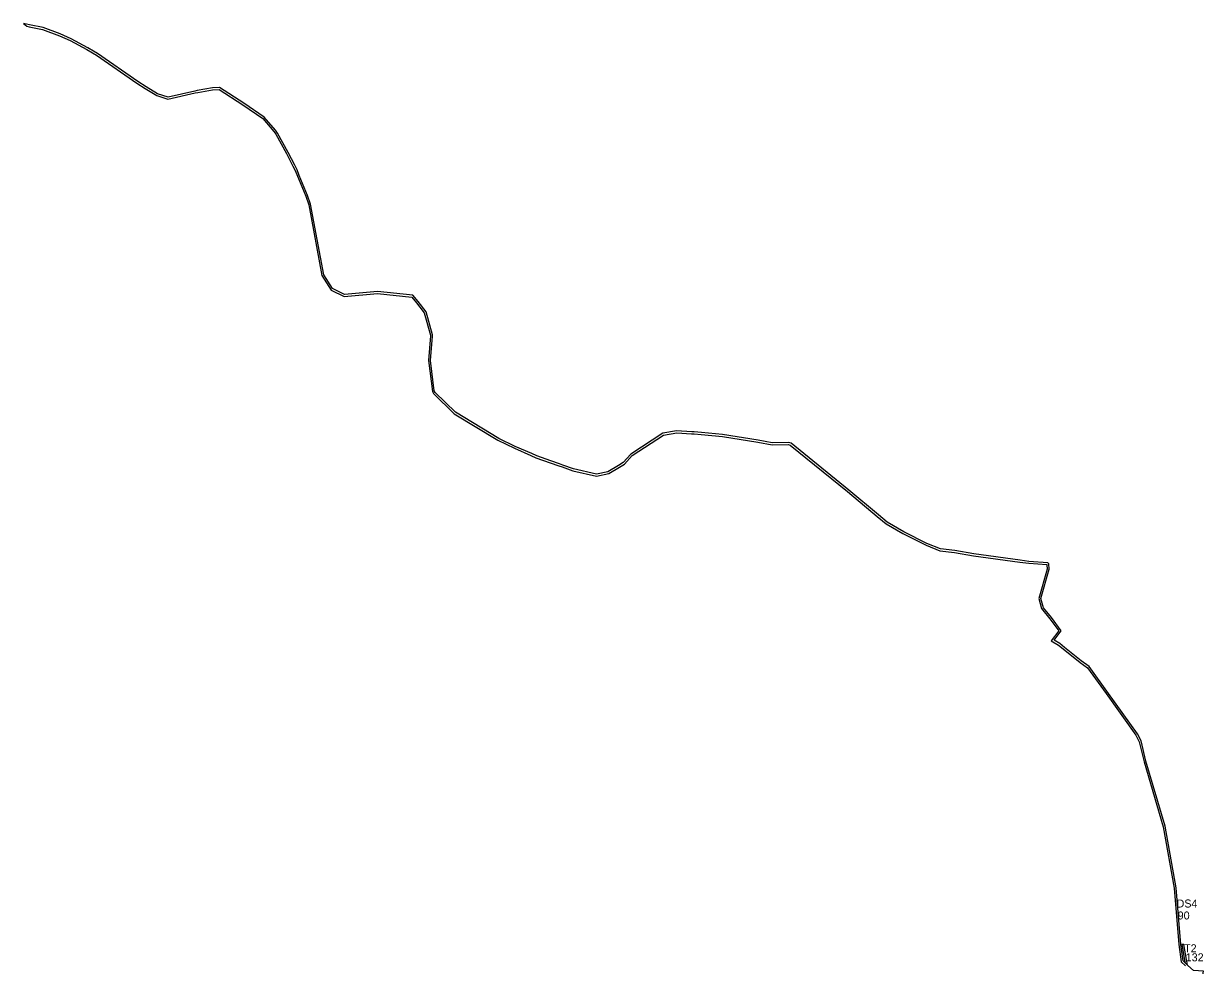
# Model space of a CAD drawing. Extents: x -477001 to -465642, y -1158278 to -1150672.
# Drawn here: x -477001 to -475233, y -1152085 to -1150672 of the extents above; entities that cross this region are included whole.
import ezdxf

# ---------------------------------------------------------------- set-up
doc = ezdxf.new("R2010")
doc.units = 0
for name, color, linetype in [('VPS_id', 7, 'Continuous'), ('VPS_n', 7, 'Continuous'), ('vyvlastneni_n', 7, 'Continuous')]:
    doc.layers.add(name, color=color, linetype=linetype)

msp = doc.modelspace()

# ---------------------------------------------------------------- linework, layer by layer
at = {"layer": 'VPS_n'}
for p, q in [((-477001.2, -1150672.5), (-476996.6, -1150676.4)), ((-475449.4, -1151582.8), (-475460.9, -1151597.8)), ((-475456.5, -1151596.9), (-475445.7, -1151582.8)), ((-475406.2, -1151638.6), (-475378.6, -1151677.1)), ((-475375, -1151677.1), (-475404, -1151636.5)), ((-475328.8, -1151749.3), (-475321.6, -1151779.5)), ((-475318.7, -1151778.7), (-475326, -1151748.2)), ((-475261.9, -1152053.4), (-475265, -1152053.3)), ((-475265, -1152053.3), (-475261, -1152076.8)), ((-475258.1, -1152076), (-475261.9, -1152053.4)), ((-475265.9, -1152079.5), (-475259.5, -1152085.3)), ((-475260, -1152080.8), (-475263, -1152078)), ((-475261, -1152076.8), (-475260.3, -1152079.1)), ((-475260.3, -1152079.1), (-475260, -1152080.8)), ((-475256.7, -1152083.9), (-475260, -1152080.8)), ((-475260, -1152080.8), (-475256.7, -1152083.9)), ((-475258.1, -1152076.1), (-475258.1, -1152076)), ((-475257.4, -1152078.2), (-475258.1, -1152076.1)), ((-475256.7, -1152083.9), (-475256.5, -1152084.1)), ((-475256.5, -1152084.1), (-475256.5, -1152084.1))]:
    msp.add_line(p, q, dxfattribs=at)
for points in [[(-476718.2, -1150768.8), (-476740.8, -1150772.9), (-476744.5, -1150773.6), (-476784.7, -1150782.8), (-476800.5, -1150777.7), (-476817.6, -1150767.5), (-476830, -1150759.4), (-476890.5, -1150717.2), (-476896.5, -1150713.7), (-476904.7, -1150708.7), (-476929.9, -1150695.2), (-476946.4, -1150688), (-476972.1, -1150678.5), (-476992.2, -1150674.1), (-477001.2, -1150672.5)], [(-476996.6, -1150676.4), (-476992.8, -1150677.1), (-476973, -1150681.4), (-476947.5, -1150690.8), (-476931.2, -1150697.9), (-476906.2, -1150711.3), (-476898.1, -1150716.3), (-476892.1, -1150719.8), (-476831.7, -1150761.9), (-476819.2, -1150770), (-476801.7, -1150780.5), (-476784.9, -1150785.9), (-476743.9, -1150776.5), (-476740.2, -1150775.8), (-476717.9, -1150771.8)], [(-475445.7, -1151582.8), (-475460.3, -1151563.2), (-475472.4, -1151548.3), (-475476.3, -1151534.3), (-475463.9, -1151490.8), (-475464.3, -1151482.7), (-475466, -1151480.9), (-475494.2, -1151478.9), (-475507.2, -1151477.2), (-475576.5, -1151467.6), (-475605.2, -1151462.8), (-475626.9, -1151460.1), (-475647, -1151452.1), (-475681.7, -1151434.5), (-475706.7, -1151420), (-475719.8, -1151409.3), (-475764.2, -1151371.9), (-475850.4, -1151301.7), (-475854, -1151300.5), (-475878.9, -1151301.2), (-475900.1, -1151297.2), (-475953.3, -1151288.5), (-475985.1, -1151285.7), (-475995.8, -1151284.8), (-475999.7, -1151284.6), (-476022.3, -1151283.2), (-476042.9, -1151286.7), (-476091.1, -1151317.9), (-476102.2, -1151330.7), (-476109.6, -1151335), (-476125.2, -1151344.5), (-476142.4, -1151347.9), (-476176.8, -1151340.1), (-476193, -1151334.4), (-476197.9, -1151332.7), (-476210.9, -1151328.2), (-476231.9, -1151320.7), (-476239.5, -1151317.2), (-476264.1, -1151306.5), (-476289, -1151294.4), (-476353.8, -1151255), (-476384.3, -1151225.5), (-476385.5, -1151223.1), (-476391.4, -1151177.6), (-476388.2, -1151141.2), (-476388, -1151139.4), (-476397.8, -1151104.9), (-476409.8, -1151089.1), (-476417.6, -1151079.8), (-476470.7, -1151074.2), (-476520.3, -1151078.5), (-476538.3, -1151069.8), (-476551.3, -1151049.3), (-476570.9, -1150943.2), (-476575.5, -1150930.1), (-476588, -1150900.4), (-476591.3, -1150891.6), (-476594.8, -1150884.9), (-476604.5, -1150866), (-476620.6, -1150837), (-476623.5, -1150832.4), (-476640.6, -1150812.6), (-476670.9, -1150791.7), (-476707.5, -1150768.5), (-476718.2, -1150768.8)], [(-476717.9, -1150771.8), (-476708.3, -1150771.5), (-476672.5, -1150794.2), (-476642.7, -1150814.8), (-476625.9, -1150834.2), (-476623.2, -1150838.5), (-476607.2, -1150867.4), (-476597.4, -1150886.3), (-476594, -1150892.9), (-476590.8, -1150901.5), (-476578.3, -1150931.2), (-476573.8, -1150944), (-476554.2, -1151050.4), (-476540.4, -1151072.1), (-476520.8, -1151081.5), (-476470.8, -1151077.2), (-476419.1, -1151082.6), (-476412.2, -1151091), (-476400.6, -1151106.3), (-476391.1, -1151139.7), (-476391.2, -1151140.9), (-476394.4, -1151177.7), (-476388.4, -1151223.9), (-476386.8, -1151227.3), (-476355.6, -1151257.4), (-476290.4, -1151297.1), (-476265.4, -1151309.3), (-476240.7, -1151320), (-476233.1, -1151323.5), (-476211.9, -1151331), (-476198.9, -1151335.6), (-476193.9, -1151337.3), (-476177.7, -1151343), (-476142.5, -1151350.9), (-476124.1, -1151347.3), (-476108.1, -1151337.6), (-476100.2, -1151333.1), (-476089.1, -1151320.2), (-476041.8, -1151289.6), (-476022.1, -1151286.3), (-475999.9, -1151287.6), (-475996.1, -1151287.8), (-475985.3, -1151288.7), (-475953.7, -1151291.5), (-475900.6, -1151300.2), (-475879.1, -1151304.2), (-475854.5, -1151303.5), (-475851.9, -1151304.4), (-475766.1, -1151374.2), (-475721.7, -1151411.6), (-475708.4, -1151422.5), (-475683.2, -1151437.2), (-475648.2, -1151454.8), (-475627.6, -1151463.1), (-475605.6, -1151465.8), (-475577, -1151470.6), (-475507.6, -1151480.2), (-475494.5, -1151481.8), (-475467.4, -1151483.8), (-475467.3, -1151484), (-475467, -1151490.5), (-475479.4, -1151534.3), (-475475.2, -1151549.7), (-475462.7, -1151565), (-475449.4, -1151582.8)], [(-475460.9, -1151597.8), (-475449.7, -1151604.6), (-475442.7, -1151610.1), (-475417.4, -1151630.5), (-475406.2, -1151638.6)], [(-475404, -1151636.5), (-475415.6, -1151628.1), (-475440.8, -1151607.8), (-475448, -1151602.1), (-475456.5, -1151596.9)], [(-475378.6, -1151677.1), (-475334.1, -1151739.3), (-475328.8, -1151749.3)], [(-475326, -1151748.2), (-475331.6, -1151737.7), (-475375, -1151677.1)], [(-475321.6, -1151779.5), (-475293, -1151876.7), (-475276.6, -1151969), (-475269.2, -1152053.6), (-475265.9, -1152079.5)], [(-475263, -1152078), (-475266.2, -1152053.3), (-475273.6, -1151968.6), (-475290.1, -1151876.1), (-475318.7, -1151778.7)], [(-475256.5, -1152084.1), (-475257.4, -1152078.4), (-475257.4, -1152078.2)], [(-475245.1, -1152165.1), (-475244.5, -1152159.7), (-475239.6, -1152134.5), (-475232.6, -1152093.5), (-475247.3, -1152092.5), (-475255.7, -1152084.7), (-475256.5, -1152084.1), (-475256.7, -1152083.9)]]:
    msp.add_lwpolyline(points, dxfattribs=at)
at = {"layer": 'vyvlastneni_n'}
for p, q in [((-477001.2, -1150672.5), (-476996.6, -1150676.4)), ((-475449.4, -1151582.8), (-475460.9, -1151597.8)), ((-475456.5, -1151596.9), (-475445.7, -1151582.8)), ((-475406.2, -1151638.6), (-475378.6, -1151677.1)), ((-475375, -1151677.1), (-475404, -1151636.5)), ((-475328.8, -1151749.3), (-475321.6, -1151779.5)), ((-475318.7, -1151778.7), (-475326, -1151748.2)), ((-475261.9, -1152053.4), (-475265, -1152053.3)), ((-475265, -1152053.3), (-475261, -1152076.8)), ((-475258.1, -1152076), (-475261.9, -1152053.4)), ((-475265.9, -1152079.5), (-475259.5, -1152085.3)), ((-475260, -1152080.8), (-475263, -1152078)), ((-475261, -1152076.8), (-475260.3, -1152079.1)), ((-475260.3, -1152079.1), (-475260, -1152080.8)), ((-475256.7, -1152083.9), (-475260, -1152080.8)), ((-475260, -1152080.8), (-475256.7, -1152083.9)), ((-475258.1, -1152076.1), (-475258.1, -1152076)), ((-475257.4, -1152078.2), (-475258.1, -1152076.1)), ((-475256.7, -1152083.9), (-475256.5, -1152084.1)), ((-475256.5, -1152084.1), (-475256.5, -1152084.1))]:
    msp.add_line(p, q, dxfattribs=at)
for points in [[(-476718.2, -1150768.8), (-476740.8, -1150772.9), (-476744.5, -1150773.6), (-476784.7, -1150782.8), (-476800.5, -1150777.7), (-476817.6, -1150767.5), (-476830, -1150759.4), (-476890.5, -1150717.2), (-476896.5, -1150713.7), (-476904.7, -1150708.7), (-476929.9, -1150695.2), (-476946.4, -1150688), (-476972.1, -1150678.5), (-476992.2, -1150674.1), (-477001.2, -1150672.5)], [(-476996.6, -1150676.4), (-476992.8, -1150677.1), (-476973, -1150681.4), (-476947.5, -1150690.8), (-476931.2, -1150697.9), (-476906.2, -1150711.3), (-476898.1, -1150716.3), (-476892.1, -1150719.8), (-476831.7, -1150761.9), (-476819.2, -1150770), (-476801.7, -1150780.5), (-476784.9, -1150785.9), (-476743.9, -1150776.5), (-476740.2, -1150775.8), (-476717.9, -1150771.8)], [(-475445.7, -1151582.8), (-475460.3, -1151563.2), (-475472.4, -1151548.3), (-475476.3, -1151534.3), (-475463.9, -1151490.8), (-475464.3, -1151482.7), (-475466, -1151480.9), (-475494.2, -1151478.9), (-475507.2, -1151477.2), (-475576.5, -1151467.6), (-475605.2, -1151462.8), (-475626.9, -1151460.1), (-475647, -1151452.1), (-475681.7, -1151434.5), (-475706.7, -1151420), (-475719.8, -1151409.3), (-475764.2, -1151371.9), (-475850.4, -1151301.7), (-475854, -1151300.5), (-475878.9, -1151301.2), (-475900.1, -1151297.2), (-475953.3, -1151288.5), (-475985.1, -1151285.7), (-475995.8, -1151284.8), (-475999.7, -1151284.6), (-476022.3, -1151283.2), (-476042.9, -1151286.7), (-476091.1, -1151317.9), (-476102.2, -1151330.7), (-476109.6, -1151335), (-476125.2, -1151344.5), (-476142.4, -1151347.9), (-476176.8, -1151340.1), (-476193, -1151334.4), (-476197.9, -1151332.7), (-476210.9, -1151328.2), (-476231.9, -1151320.7), (-476239.5, -1151317.2), (-476264.1, -1151306.5), (-476289, -1151294.4), (-476353.8, -1151255), (-476384.3, -1151225.5), (-476385.5, -1151223.1), (-476391.4, -1151177.6), (-476388.2, -1151141.2), (-476388, -1151139.4), (-476397.8, -1151104.9), (-476409.8, -1151089.1), (-476417.6, -1151079.8), (-476470.7, -1151074.2), (-476520.3, -1151078.5), (-476538.3, -1151069.8), (-476551.3, -1151049.3), (-476570.9, -1150943.2), (-476575.5, -1150930.1), (-476588, -1150900.4), (-476591.3, -1150891.6), (-476594.8, -1150884.9), (-476604.5, -1150866), (-476620.6, -1150837), (-476623.5, -1150832.4), (-476640.6, -1150812.6), (-476670.9, -1150791.7), (-476707.5, -1150768.5), (-476718.2, -1150768.8)], [(-476717.9, -1150771.8), (-476708.3, -1150771.5), (-476672.5, -1150794.2), (-476642.7, -1150814.8), (-476625.9, -1150834.2), (-476623.2, -1150838.5), (-476607.2, -1150867.4), (-476597.4, -1150886.3), (-476594, -1150892.9), (-476590.8, -1150901.5), (-476578.3, -1150931.2), (-476573.8, -1150944), (-476554.2, -1151050.4), (-476540.4, -1151072.1), (-476520.8, -1151081.5), (-476470.8, -1151077.2), (-476419.1, -1151082.6), (-476412.2, -1151091), (-476400.6, -1151106.3), (-476391.1, -1151139.7), (-476391.2, -1151140.9), (-476394.4, -1151177.7), (-476388.4, -1151223.9), (-476386.8, -1151227.3), (-476355.6, -1151257.4), (-476290.4, -1151297.1), (-476265.4, -1151309.3), (-476240.7, -1151320), (-476233.1, -1151323.5), (-476211.9, -1151331), (-476198.9, -1151335.6), (-476193.9, -1151337.3), (-476177.7, -1151343), (-476142.5, -1151350.9), (-476124.1, -1151347.3), (-476108.1, -1151337.6), (-476100.2, -1151333.1), (-476089.1, -1151320.2), (-476041.8, -1151289.6), (-476022.1, -1151286.3), (-475999.9, -1151287.6), (-475996.1, -1151287.8), (-475985.3, -1151288.7), (-475953.7, -1151291.5), (-475900.6, -1151300.2), (-475879.1, -1151304.2), (-475854.5, -1151303.5), (-475851.9, -1151304.4), (-475766.1, -1151374.2), (-475721.7, -1151411.6), (-475708.4, -1151422.5), (-475683.2, -1151437.2), (-475648.2, -1151454.8), (-475627.6, -1151463.1), (-475605.6, -1151465.8), (-475577, -1151470.6), (-475507.6, -1151480.2), (-475494.5, -1151481.8), (-475467.4, -1151483.8), (-475467.3, -1151484), (-475467, -1151490.5), (-475479.4, -1151534.3), (-475475.2, -1151549.7), (-475462.7, -1151565), (-475449.4, -1151582.8)], [(-475460.9, -1151597.8), (-475449.7, -1151604.6), (-475442.7, -1151610.1), (-475417.4, -1151630.5), (-475406.2, -1151638.6)], [(-475404, -1151636.5), (-475415.6, -1151628.1), (-475440.8, -1151607.8), (-475448, -1151602.1), (-475456.5, -1151596.9)], [(-475378.6, -1151677.1), (-475334.1, -1151739.3), (-475328.8, -1151749.3)], [(-475326, -1151748.2), (-475331.6, -1151737.7), (-475375, -1151677.1)], [(-475321.6, -1151779.5), (-475293, -1151876.7), (-475276.6, -1151969), (-475269.2, -1152053.6), (-475265.9, -1152079.5)], [(-475263, -1152078), (-475266.2, -1152053.3), (-475273.6, -1151968.6), (-475290.1, -1151876.1), (-475318.7, -1151778.7)], [(-475256.5, -1152084.1), (-475257.4, -1152078.4), (-475257.4, -1152078.2)], [(-475245.1, -1152165.1), (-475244.5, -1152159.7), (-475239.6, -1152134.5), (-475232.6, -1152093.5), (-475247.3, -1152092.5), (-475255.7, -1152084.7), (-475256.5, -1152084.1), (-475256.7, -1152083.9)]]:
    msp.add_lwpolyline(points, dxfattribs=at)

# ---------------------------------------------------------------- texts
at = {"layer": 'VPS_id'}
for s, p in [('90', (-475271.1, -1152015.8)), ('132', (-475259.1, -1152078.6))]:
    msp.add_text(s, height=12, dxfattribs=at).set_placement(p)
at = {"layer": 'VPS_n'}
for s, p in [('DS4', (-475272.8, -1151997.9)), ('T2', (-475261.5, -1152065))]:
    msp.add_text(s, height=12, dxfattribs=at).set_placement(p)

doc.saveas('drawing.dxf')
